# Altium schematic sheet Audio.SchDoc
size A4; DocumentNumber: 4; Revision: B.2(PCB.SCH); SheetNumber: 4; SheetTotal: 6
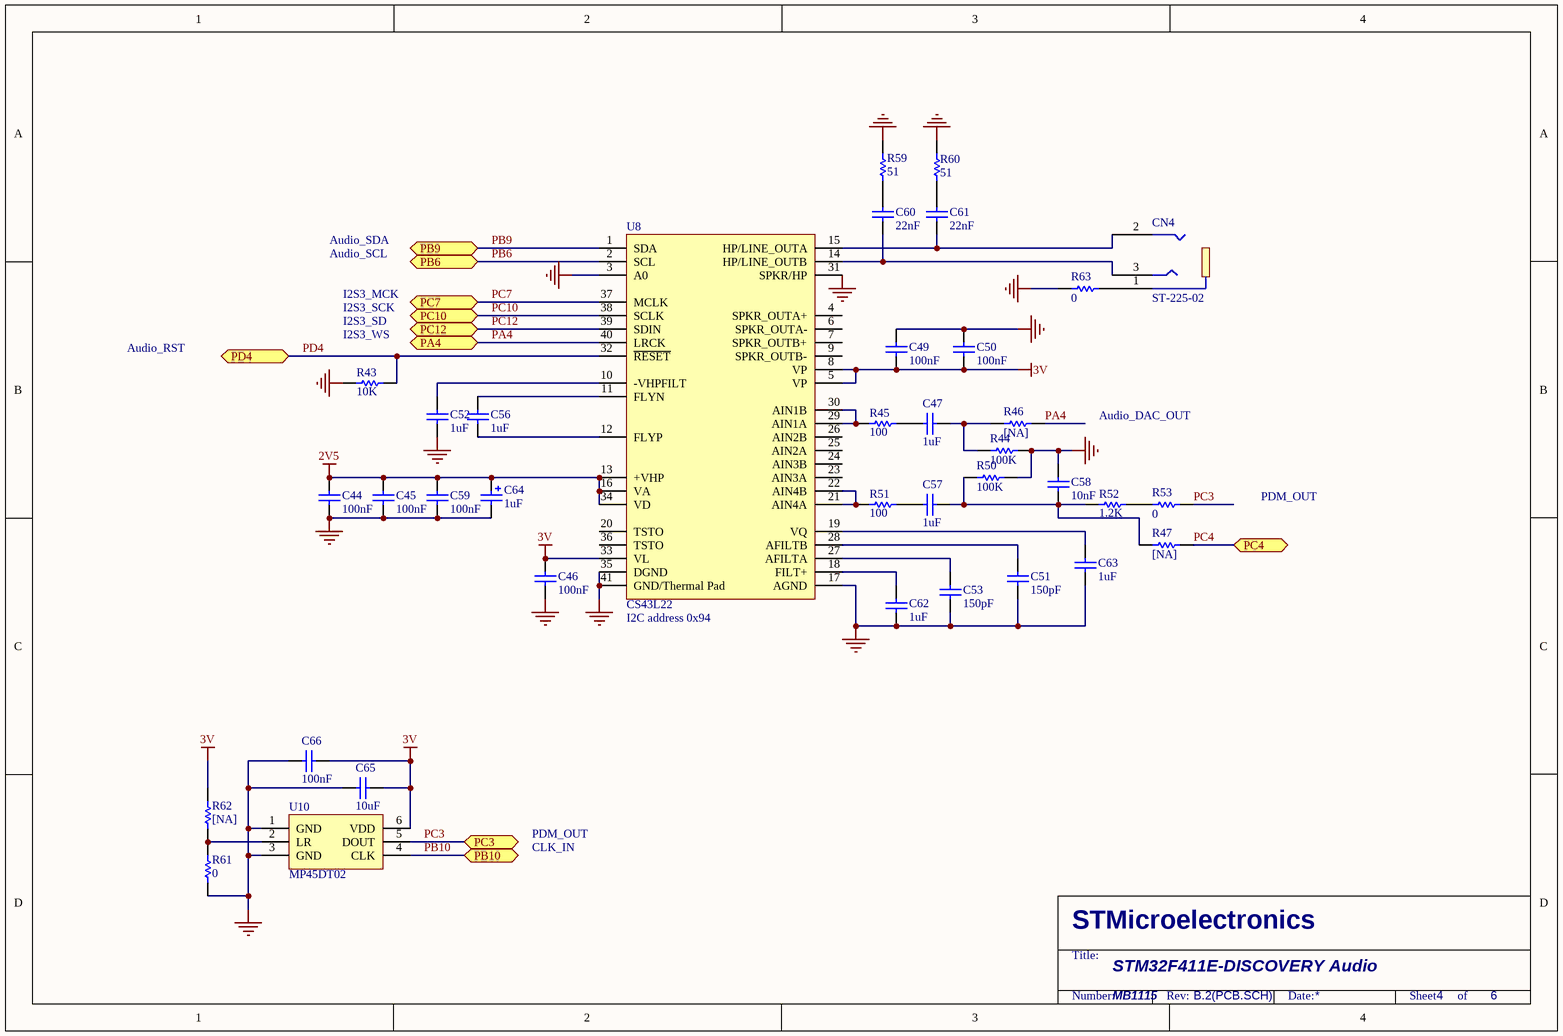
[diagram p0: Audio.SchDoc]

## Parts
C44  100nF  [0402C]
C45  100nF  [0402C]
C46  100nF  [0402C]
C47  1uF  [0603C]
C49  100nF  [0402C]
C50  100nF  [0402C]
C51  150pF  [0603C]
C52  1uF  [0603C]
C53  150pF  [0603C]
C56  1uF  [0603C]
C57  1uF  [0603C]
C58  10nF  [0603C]
C59  100nF  [0402C]
C60  22nF  [0603C]
C61  22nF  [0603C]
C62  1uF  [0603C]
C63  1uF  [0603C]
C64  1uF  [TAN-A]
C65  10uF  [0603C]
C66  100nF  [0402C]
CN4  ST-225-02  [Jack-ST-225]
R43  10K  [0402R]
R44  100K  [0402R]
R45  100  [0402R]
R46  [NA]  [0402R]
R47  [NA]  [0402R]
R50  100K  [0402R]
R51  100  [0402R]
R52  1.2K  [0402R]
R53  0  [0402R]
R59  51  [0402R]
R60  51  [0402R]
R61  0  [0402R]
R62  [NA]  [0402R]
R63  0  [0402R]
U8  CS43L22  [QFN40]
U10  MP45DT02  [HLGA-4.72-3.76-6LD]

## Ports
PA4, PB6, PB9, PB10, PC3, PC4, PC7, PC10, PC12, PD4

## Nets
2V5: C44.2 C45.2 C59.2 C64.1 U8.13(+VHP) U8.16(VA) U8.34(VD)
3V: C46.2 C49.1 C50.2 C65.2 C66.2 R62.2 U8.5(VP) U8.8(VP) U8.33(VL) U10.6(VDD)
GND: C44.1 C45.1 C46.1 C49.2 C50.1 C51.1 C52.2 C53.1 C58.2 C59.1 C62.1 C63.1 C64.2 C65.1 C66.1 R43.2 R44.2 R50.2 R59.2 R60.1 R61.1 R63.1 U8.3(A0) U8.17(AGND) U8.31(SPKR/HP) U8.35(DGND) U8.41(GND/Thermal_Pad) U10.1(GND) U10.3(GND)
PA4: R46.2 U8.40(LRCK) ; port PA4
PB6: U8.2(SCL) ; port PB6
PB9: U8.1(SDA) ; port PB9
PB10: U10.4(CLK) ; port PB10
PC3: R53.2 U10.5(DOUT) ; port PC3
PC4: R47.2 ; port PC4
PC7: U8.37(MCLK) ; port PC7
PC10: U8.38(SCLK) ; port PC10
PC12: U8.39(SDIN) ; port PC12
PD4: R43.1 U8.32(~{RESET}) ; port PD4
NetC47_1: C47.1 R45.1
NetC47_2: C47.2 R44.1 R46.1
NetC51_2: C51.2 U8.28(AFILTB)
NetC52_1: C52.1 U8.10(-VHPFILT)
NetC53_2: C53.2 U8.27(AFILTA)
NetC56_1: C56.1 U8.12(FLYP)
NetC56_2: C56.2 U8.11(FLYN)
NetC57_1: C57.1 R51.1
NetC57_2: C57.2 C58.1 R47.1 R50.1 R52.1
NetC60_1: C60.1 CN4.3 U8.14(HP/LINE_OUTB)
NetC60_2: C60.2 R59.1
NetC61_1: C61.1 CN4.2 U8.15(HP/LINE_OUTA)
NetC61_2: C61.2 R60.2
NetC62_2: C62.2 U8.18(FILT+)
NetC63_2: C63.2 U8.19(VQ)
NetCN4_1: CN4.1 R63.2
NetR45_2: R45.2 U8.29(AIN1A) U8.30(AIN1B)
NetR51_2: R51.2 U8.21(AIN4A) U8.22(AIN4B)
NetR52_2: R52.2 R53.1
NetR61_2: R61.2 R62.1 U10.2(LR)

Not connected (* = marked no-connect by the designer): U8 4(SPKR_OUTA+) 6(SPKR_OUTA-) 7(SPKR_OUTB+) 9(SPKR_OUTB-) 20(TSTO) 23(AIN3A) 24(AIN3B) 25(AIN2A) 26(AIN2B) 36(TSTO)

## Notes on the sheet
- Audio_SDA
- Audio_SCL
- I2S3_MCK
- I2S3_SCK
- Audio_RST
- (near R43) I2S3_WS
- I2S3_SD
- Audio_DAC_OUT
- PDM_OUT
- (near U8) I2C address 0x94
- CLK_IN
- STM32F411E-DISCOVERY Audio
- MB1115

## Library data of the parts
C44-C46 C49 C50 C59 C66 = Cap_100nF_X7R_10%_0402: Capacitor,100nF,16V,X7R,10%,0402,YAGEO; Manuf_Part_1: CC0402KRX7R7BB104
C47 C52 C56 C57 C62 C63 = Cap_1uF_X5R_10%_0603: Capacitor,1uF,16V,X5R,10%,0603,YAGEO; Manuf_Part_1: CC0603KRX5R7BB105
C51 C53 = Cap_150pF_NPO_5%_0603: Capacitor,150pF,50V,NPO,5%,0603,YAGEO; Order: CC0603JRNPO9BN151
C58 = Cap_10nF_X7R_10%_0603: Capacitor,10nF,50V,X7R,10%,0603,YAGEO; Manuf_Part_1: CC0603KRX7R9BB103
C60 C61 = Cap_22nF_X7R_10%_0603: Capacitor,22nF,50V,X7R,10%,0603,YAGEO; Manuf_Part_1: CC0603KRX7R9BB223
C64 = Cap_1uF_POL_10%_TANA: Polarized Capacitor,1uF,16V,10%,typeA,AVX; Manuf_Part_1: TAJA105K016R
C65 = Cap_10uF_X5R_10%_0603: Capacitor,10uF,6.3V,X5R,20%,0603,YAGEO; Manuf_Part_1: CC0603KRX5R5BB106
CN4 = ST-225-02: Connector Jack 35mm; Manuf_1: XIEJIA Electronics
R43-R45 R50 R51 R59 R60 = res1: Resistor; Value: 1K
R46 R47 R62 = Res_NA_0402: Resistor,[NA],0402; Fitted: NO
R52 = res1: Resistor
R53 R61 R63 = Res_0_0402: Resistor,0,0402
U8 = CS43L22: Low Power, Stereo DAC w/Headphone & Speaker Amps; Manuf_1: Cirrus; Order: CS43L22-CNZ
U10 = MP45DT02: MEMS audio sensor, omnidirectional digital microphone; Manuf_1: STM; Manuf_Part_1: MP45DT02TR; Provided: ST; Ref St: 9188006; ECCN_US/EU: EAR99/NEC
